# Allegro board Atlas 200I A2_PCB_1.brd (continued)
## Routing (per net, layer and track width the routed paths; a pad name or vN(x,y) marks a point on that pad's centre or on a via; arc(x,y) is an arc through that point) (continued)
VBUS_USB_TYPEC: length 2.5
  TOP w0.254: J4.21 104.6,6.16 J4.4 ; J4.16 107.1,6.16 J4.9
  vias: v1(101.04,10.62)
/CLKREQ_M2: length 2.7
  TOP w0.203: R34.1 R26.1 113.92,30.6 113.96,30.64 J1.52
/CLKREQ_WIFI: length 140.6
  TOP w0.203: v1(7.49,74.8) R70.1 7.39,75.54 6.58,76.35 R42.2 ; J16.319 98.5,59 v1(99.06,59.56)
  BOTTOM w0.203: v1(99.06,59.56) 99.63,60.13 99.63,61.21 97.82,63.02 74.23,63.02 69.38,58.17 67.12,58.17 66.59,58.71 66.59,60.24 65.93,60.89 64.38,60.89 64.11,61.16 64.11,66.76 64.6,67.95 65.95,69.29 69.15,70.62 71.41,72.88 71.41,73.26 71.14,73.53 70.58,73.53 67.79,76.32 67.79,76.36 66.38,77.77 60.38,77.77 54.47,71.87 30.07,71.87 29.85,72.09 24.27,72.09 22.48,70.29 22.48,66.92 22.21,66.65 16.41,66.65 11.91,71.15 9.45,71.15 7.49,73.1 v1(7.49,74.8)
/EMMC_RESET: length 64.2
  TOP w0.203: J16.203 v1(47,59.61) ; R79.1 22.56,93.65 22.81,93.9 22.81,95.93 v1(22.21,96.52) ; v1(43.34,82.07) 44.07,82.07 44.69,81.45 R202.2 45.13,80.92 45.34,80.72 45.34,79.15 v1(45.97,78.52)
  ART03 w0.203: v1(45.97,78.52) 46.51,77.99 46.51,73.63 47.35,72.8 47.35,63.04 47,62.7 v1(47,59.61)
  ART04 w0.203: v1(43.34,82.07) 45.04,83.77 45.04,86 35.61,95.43 29.27,95.43 27.57,97.13 22.82,97.13 v1(22.21,96.52)
/EMMC_RESET_R: length 17.4
  TOP w0.127: v1(8.06,97.03) 7.95,96.91 U27.K5
  TOP w0.203: C87.2 R77.2 v1(22.16,95.1)
  ART04 w0.203: v1(22.16,95.1) 10.79,95.1 8.87,97.03 v1(8.06,97.03)
/LED_PHY0_ACT: length 71.1
  TOP w0.203: v1(8.1,57.53) 8.35,57.28 8.35,56.01 8.56,55.79 U1.37 ; v1(35,26.67) R365.2 ; R98.2 R140.1 v1(22.05,63.7) 21.72,63.38 21.72,63.25 20.93,62.46 15.21,62.46 v1(15.04,62.28)
  BOTTOM w0.203: v1(15.04,62.28) 14.35,61.59 9.73,61.59 8.28,60.15 8.28,57.72 v1(8.1,57.53)
  BOTTOM w0.254: v1(22.05,63.7) 24,61.75 24,56.64 18.75,51.38 18.75,44.81 29.14,34.41 32.09,34.41 35.18,31.32 35.18,26.85 v1(35,26.67)
/LED_PHY0_LINK: length 103.7
  TOP w0.203: v1(8.86,57.53) 9.26,57.12 9.73,57.12 9.95,56.9 U1.35 ; R99.2 v1(24.46,71.63) R138.1 ; v1(35,22.61) R366.2
  ART03 w0.203: v1(24.46,71.63) 23.57,71.63 22.96,71.02 16.48,71.02 8.86,63.39 v1(8.86,57.53)
  BOTTOM w0.203: v1(24.46,71.63) 29.73,71.63 35.05,66.31 35.05,61.91 30.06,56.92 26.31,56.92 19.18,49.79 19.18,45.61 28.8,35.99 31.49,35.99 36.32,31.15 36.32,30.11 35.66,29.44 35.66,26.68 35.12,26.15 34.85,26.15 34.54,25.84 34.54,23.06 v1(35,22.61)
/LED_PHY1_ACT: length 31.4
  TOP w0.203: v1(35,25.65) R367.2 ; v1(47.8,37.29) 47.48,37.61 47.48,38.61 47.93,39.07 49.38,39.07 49.76,38.68 R146.1 49.99,38.71 51.94,38.71 52.17,38.94 R154.2 52.43,39.24 54.48,37.19 54.48,36.57 54.69,36.36 U2.37
  BOTTOM w0.203: v1(47.8,37.29) 46.94,37.29 46.48,36.83 44.31,36.83 42.57,35.09 42.57,33.77 39.12,30.32 38.63,30.12 37.8,29.29 37.8,27.99 35.46,25.65 v1(35,25.65)
/LED_PHY1_LINK: length 38.5
  TOP w0.203: v1(35,23.62) R368.2 ; U2.35 56.11,37.61 v1(55.88,37.85) 55.61,38.12 54.72,38.12 53.54,39.29 53.54,41.5 53.26,41.79 R155.2 53.11,42.04 R144.1
  BOTTOM w0.203: v1(55.88,37.85) 55.55,38.18 50.17,38.18 48.36,36.37 47.25,36.37 46.84,35.97 44.67,35.97 43.43,34.73 43.43,29.85 42.55,28.96 42.55,28.07 38.1,23.62 v1(35,23.62)
/OC0_USB30_REAR_1: length 141.9
  TOP w0.203: v1(90.33,101.83) 90.21,101.83 89.89,102.15 U38.25 89.89,104.07 89.69,104.27 88.74,104.27 R598.1 ; v1(87.9,69.22) R545.1
  ART03 w0.203: v1(87.9,69.22) 90.2,69.22 90.3,69.11 91.76,69.11 91.85,69.03 92.23,69.03 92.32,69.11 96.98,69.11 97.28,69.42 97.28,73.2 95.83,74.65 95.83,75.73 v1(97.07,76.96)
  ART04 w0.203: v1(97.07,76.96) 97.55,76.48 99.92,76.48 100.91,75.49 100.91,74.04 101.4,73.56 108.5,73.56 108.7,73.36 117.25,73.36 119.99,70.61 122.73,70.61 122.87,70.47 123.89,70.47 125.12,71.7 126.11,71.7 130.01,75.6 130.01,77.24 129.21,78.04 129.21,82.68 130.01,83.48 130.01,83.86 129.78,84.09 129.78,95.93 130.72,96.87 130.72,100.62 129.79,101.55 123.95,101.55 123.52,101.12 121.58,101.12 120.89,101.8 106.72,101.8 104.43,99.52 99.94,99.52 99.39,100.07 99.39,104.51 97.47,106.43 95.15,106.43 93.57,108 93.57,108.4 93.29,108.69 92.89,108.69 90.33,106.13 v1(90.33,101.83)
/OC0_USB30_REAR_2: length 54.9
  TOP w0.203: v1(72.84,70.99) 73.07,70.76 R645.1 ; R646.1 93.9,101.09 v1(93.55,101.09) 93.55,101.14 93.32,101.37 U38.18
  ART04 w0.203: v1(84.62,101.51) 85.77,100.36 92.81,100.36 v1(93.55,101.09)
  BOTTOM w0.203: v1(84.62,101.51) 83.81,100.71 83.81,99.64 79.4,95.22 79.4,83.78 78.32,82.7 77.23,82.7 74.47,79.95 74.47,77.25 73.88,76.65 73.69,76.65 72.54,75.5 72.54,72.31 72.84,72 v1(72.84,70.99)
/OC1_USB30_REAR_1: length 14.3
  TOP w0.203: R546.2 R544.1 86.45,72.91 86.2,73.16 86.12,73.16 v1(85.8,73.48) ; U36.67 91.68,80.22 91.88,80.02 91.88,79.5 v1(92.14,79.25)
  ART03 w0.203: v1(85.8,73.48) 86.12,73.81 86.12,74.21 86.94,75.03 87.81,75.03 92.02,79.25 v1(92.14,79.25)
/OC1_USB30_REAR_2: length 19.8
  TOP w0.203: U36.10 95.35,76.4 95.55,76.61 v1(95.83,76.61) ; R644.1 R643.2 82.7,70.76 v1(84.58,72.64)
  ART03 w0.203: v1(84.58,72.64) 87.2,72.64 88.14,73.58 94.77,73.58 95.38,74.2 95.38,76.15 v1(95.83,76.61)
/OC_USB30_REAR_1: length 76.6
  TOP w0.203: v1(48.26,31.5) 48.26,30.94 R647.1 47.44,30.85 U8.3 ; R544.2 R545.2 86,68.76 82.27,68.76 82.02,69.01 70.43,69.01 v1(69.98,69.47)
  ART03 w0.203: v1(53.09,40.39) 53.09,36.32 v1(48.26,31.5) ; v1(69.98,69.47) 69.56,69.89 65.96,69.89 62.17,66.1 62.17,55.42 57.45,50.7 v1(54.69,50.7)
  ART04 w0.203: v1(53.09,40.39) 53.54,40.84 53.54,41.51 52.17,42.88 52.17,44.19 53.04,45.06 55.59,45.06 57.15,46.62 57.15,47.83 54.69,50.29 v1(54.69,50.7)
/OC_USB30_REAR_2: length 105.8
  TOP w0.203: v1(59.44,16.76) 59.44,16.13 59.23,15.93 R648.1 58.56,16.29 U9.3 ; R644.2 R645.2 71.35,69.95 v1(70.87,69.47)
  ART03 w0.203: v1(57.02,41.27) 58.04,42.29 58.04,45.55 57.81,45.77 57.81,46.17 58.32,46.68 58.32,47.6 62.58,51.86 62.58,65.93 66.13,69.48 69.32,69.48 69.79,69.01 70.41,69.01 v1(70.87,69.47) ; v1(59.44,16.76) 54.51,16.76 50.27,21 47.88,21 44.33,24.56 40.57,24.56 39.99,25.14 39.99,27.67 39.75,27.91 38.36,27.91 37.84,28.42 37.84,29.33 38.2,29.69 38.85,29.69 44,34.84 44,37.9 v1(45.09,38.99)
  BOTTOM w0.203: v1(57.02,41.27) 57.02,41.73 56.16,42.6 53.29,42.6 52.32,41.63 49.63,41.63 49.58,41.68 49.18,41.68 46.69,39.19 45.29,39.19 v1(45.09,38.99)
/PERST_M2: length 39.4
  TOP w0.203: J16.296 103.75,50.47 v1(103.58,50.65) ; R12.2 R678.1 v1(119.25,68.23)
  ART03 w0.203: v1(103.58,50.65) 104.36,51.44 104.36,55.42 108.46,59.52 108.46,71.41 109.12,72.06 v1(109.12,72.39)
  ART04 w0.203: v1(119.25,68.23) 115.86,71.63 109.88,71.63 v1(109.12,72.39)
/PERST_M2_R: length 65.4
  TOP w0.203: U21.13 118.75,76.51 v1(119.08,76.18) ; R32.1 R27.1 C34.1 111.71,31.59 v1(111.83,31.46)
  TOP w0.254: R23.2 v1(111.83,31.46)
  ART03 w0.203: v1(108.25,76.94) 109.33,76.94 109.73,76.54 109.73,72.02 109.27,71.57 109.27,62.56 v1(111.43,60.4)
  ART04 w0.203: v1(108.25,76.94) 109.6,76.94 110.9,75.64 118.53,75.64 v1(119.08,76.18)
  BOTTOM w0.203: v1(111.83,31.46) 111.83,33.1 111.05,33.88 111.05,44.5 110.52,45.03 110.52,59.49 v1(111.43,60.4)
/PERST_WIFI: length 35.3
  TOP w0.203: R626.1 110.52,76.47 R566.2 ; v1(106.6,54.2) 106.6,54.1 104.25,51.75 J16.294
  TOP w0.254: R566.2 v1(111.45,76.32)
  ART03 w0.203: v1(111.45,76.32) 111.45,69.01 111.02,68.58 111.02,66.69 112.94,64.78 112.94,58.94 111.37,57.37 111.24,57.37 109.95,56.08 108.02,56.08 106.6,54.66 v1(106.6,54.2)
/PERST_WIFI_R: length 93.1
  TOP w0.203: v1(7.11,80.9) 7.11,82.25 8.26,83.39 9.14,83.39 9.42,83.67 J2.52 9.42,85.67 9.22,85.88 8.53,85.88 7.86,86.55 R39.1 ; R618.2 73.8,79.49 v1(73.79,79.5)
  ART03 w0.203: v1(52.45,79.63) 52.45,72.75 v1(52.04,72.35)
  ART04 w0.203: v1(7.11,80.9) 7.16,80.85 7.16,77.45 7.01,77.3 7.01,74.6 7.93,73.69 9.47,73.69 12.01,71.15 24.66,71.15 24.96,71.44 51.14,71.44 v1(52.04,72.35)
  BOTTOM w0.203: v1(52.45,79.63) 54.38,81.55 71.73,81.55 v1(73.79,79.5)
/PEWAKE_M2: length 3.7
  TOP w0.203: J1.54 114.24,30.14 114.05,29.95 114.05,29.1 113.84,28.89 R33.1 R28.1
/PEWAKE_WIFI: length 7
  TOP w0.203: v1(99.06,58.29) 99,58.23 J16.317 ; R625.1 R571.2 v1(98.6,61.5)
  ART03 w0.203: v1(99.06,58.29) 98.6,58.75 v1(98.6,61.5)
/PEWAKE_WIFI_R: length 86.1
  TOP w0.203: R41.2 5.41,76.35 4.6,75.54 R43.1 v1(4.45,74.8) ; R617.2 v1(73.88,83.12)
  ART03 w0.203: v1(51.18,79.63) 51.66,79.15 51.66,78.23 51.56,78.13 51.56,71.56 v1(52.04,71.08)
  ART04 w0.203: v1(4.45,74.8) 7.87,71.37 9.93,71.37 11.43,69.88 24.71,69.88 25.82,70.99 51.33,70.99 51.34,71 51.96,71 v1(52.04,71.08)
  BOTTOM w0.203: v1(51.18,79.63) 54.05,82.5 73.25,82.5 v1(73.88,83.12)
/RST_USB_HUB_R: length 5.5
  TOP w0.203: U38.24 90.29,104.81 R633.2 C367.1 ; C367.1 R639.2 ; C367.1 90.53,106.25 R632.2
/SDIO_RESET_R: length 19.3
  TOP w0.203: v1(15.95,79.86) 16.68,79.13 J2.23 ; v1(20.95,92.08) 21.4,92.08 R79.2
  ART03 w0.203: v1(15.95,79.86) 15.34,80.47 15.34,81.38 15.44,81.48 15.44,82.22 15.44,82.22 15.44,82.39 16.55,83.5 16.55,84.09 18.39,85.92 18.39,86.38 19.38,87.38 20.57,87.38 21.44,88.24 21.44,91.59 v1(20.95,92.08)
/SDIO_WAKE_R: length 79.8
  TOP w0.203: J2.21 17.17,79.19 16.54,79.83 16.54,80.54 v1(15.95,81.13) ; J16.121 67.5,54.46 v1(67.5,54.46) ; R80.2 v1(22.23,86.36)
  ART03 w0.203: v1(15.95,81.13) 16.05,81.23 16.05,82.14 17.16,83.25 17.16,83.83 17.8,84.47 18.2,84.47 19.44,85.71 19.44,86.37 19.72,86.65 21.93,86.65 v1(22.23,86.36) ; v1(38.95,70.09) 38.95,70.7 33.94,75.71 33.94,81.75 v1(30.1,85.6)
  ART04 w0.203: v1(67.5,54.46) 67.5,54.82 65.15,57.16 65.15,59.22 54.27,70.09 v1(38.95,70.09)
  BOTTOM w0.203: v1(30.1,85.6) 22.99,85.6 v1(22.23,86.36)
/WAKE_PHY0: length 21.2
  TOP w0.203: R624.1 R569.2 R217.2 68.75,72.44 63.58,67.26 63.58,59.7 62.5,58.62 J16.141
/WAKE_PHY0_R: length 74.3
  TOP w0.203: R616.2 74.13,83.98 v1(73.88,84.23) ; v1(19.02,60.73) 19.74,60.02 20.83,60.02 R125.1 21.08,60.27 R101.1 R124.2
  ART03 w0.203: v1(19.02,60.73) 19.02,63.8 22.02,66.8 v1(22.02,67.11)
  BOTTOM w0.203: v1(22.02,67.11) 22.02,70.73 23.83,72.53 23.83,72.84 24.36,73.38 24.54,73.38 27.85,76.69 46.84,76.69 55.25,85.1 73.01,85.1 v1(73.88,84.23)
/WAKE_PHY1: length 54.4
  TOP w0.203: R621.1 v1(87.63,85.81) ; v1(99.06,60.83) 98.67,60.44 R565.2 R235.2 98,59.58 J16.321
  ART03 w0.203: v1(99.06,60.83) 99.87,61.65 99.87,66.48 102.64,69.25 102.64,74.83 102.67,74.85 102.67,80.19 101.94,80.91 101.94,83.53 v1(103.89,85.47)
  ART04 w0.203: v1(87.63,85.81) 87.17,85.81 85.99,84.63 85.99,84.23 86.29,83.93 90.47,83.93 90.73,84.2 92.31,84.2 92.79,84.68 101.69,84.68 102.48,85.47 v1(103.89,85.47)
/WAKE_PHY1_R: length 78
  TOP w0.203: R168.1 54.08,41.25 v1(54.23,41.4) 54.12,41.51 R192.2 54.35,42.04 54.68,42.37 R193.1 ; v1(73.88,85.34) 74.38,84.83 R613.2
  ART03 w0.203: v1(50.14,65.57) 50.04,65.67 v1(50.04,78.61)
  ART04 w0.203: v1(54.23,41.4) 52.58,43.05 52.58,43.5 52.85,43.76 53.59,43.76 53.85,43.51 55.37,43.51 56.67,44.81 56.67,45.06 57.1,45.49 57.48,45.49 57.76,45.77 57.76,46.28 58.27,46.79 58.27,48.98 54.55,52.7 53.36,52.7 50.87,55.19 50.87,59.79 50.14,60.53 v1(50.14,65.57)
  BOTTOM w0.203: v1(50.04,78.61) 50.04,79.22 54.41,83.59 73.88,83.59 74.33,84.04 74.33,84.88 v1(73.88,85.34)
/WAKE_UART3: length 2.9
  TOP w0.203: R44.2 17.02,88.62 17.53,89.13 R48.1
AC_IN_L: length 42.3
  TOP w0.254: v1(131.85,40.84) 132.54,40.84 132.79,40.59 132.79,40.31 132.97,40.13 C149.1 LB12.2 ; J16.306 101.25,47.15 v1(100.97,46.86)
  ART03 w0.254: v1(131.85,40.84) 131.27,40.27 130.73,40.27 130.19,40.81 130.19,44.23 127.83,46.58 112.99,46.58 112.4,46 105.95,46 104.98,45.03 102.34,45.03 100.97,46.41 v1(100.97,46.86)
AC_IN_R: length 38.9
  TOP w0.254: v1(131.09,40.84) 131.09,41.51 C148.1 130.49,41.51 130.37,41.39 LB11.2 ; J16.304 101.75,46.97 v1(101.85,46.86)
  ART03 w0.254: v1(131.09,40.84) 130.89,41.05 130.89,44.47 128.11,47.24 112.71,47.24 112.13,46.66 105.68,46.66 104.71,45.69 102.98,45.69 101.85,46.82 v1(101.85,46.86)
AC_MICBIAS0: length 43.3
  TOP w0.203: J16.300 102.75,47.62 v1(103.5,46.86) ; R314.2 v1(134.24,36.12)
  ART03 w0.203: v1(103.5,46.86) 103.63,46.99 104.17,46.99 105.13,47.96 111.59,47.96 112.17,48.54 128.64,48.54 132.18,45 132.18,42.42 133.15,41.46 133.15,37.21 v1(134.24,36.12)
BOARD_ID0: length 5.2
  TOP w0.203: U19.4 120.49,94.04 121.34,93.19 R523.2 121.54,92.89 121.74,92.68 123.37,92.68 123.62,92.94 R507.1
BOARD_ID1: length 5
  TOP w0.203: U19.5 120.6,94.69 121.08,94.21 R522.2 121.54,93.9 121.74,93.7 123.37,93.7 123.62,93.95 R506.1
BOARD_ID2: length 4.9
  TOP w0.203: R505.1 123.62,94.97 123.37,94.72 121.74,94.72 121.54,94.92 R521.2 120.81,95.22 120.7,95.34 U19.6
BOARD_ID3: length 4.9
  TOP w0.203: U19.7 120.78,95.99 121.03,96.24 R520.2 121.54,95.94 121.74,95.73 123.37,95.73 123.62,95.99 R504.1
BOARD_ID4: length 5.1
  TOP w0.203: R503.1 123.62,97 123.37,96.75 121.74,96.75 121.54,96.95 R519.2 120.92,96.64 U19.8
BOARD_ID5: length 5.2
  TOP w0.203: 121.54,98.22 R518.2 ; 121.54,98.22 121.54,97.97 121.74,97.76 123.37,97.76 123.62,98.02 R502.1 ; 121.54,98.22 120.6,97.29 U19.9
BOARD_ID6: length 5.5
  TOP w0.203: U19.10 120.39,97.94 120.88,98.42 120.88,98.63 R517.2 121.54,98.98 121.74,98.78 123.37,98.78 123.62,99.03 R501.1
BOARD_ID7: length 10
  TOP w0.203: R500.1 123.62,100.05 123.37,99.8 121.74,99.8 121.54,100 R516.2 120.73,100.3 120.17,99.75 118.08,99.75 117.55,99.21 117.55,98.65 117.75,98.45 118.28,98.45 118.41,98.59 U19.11
BOM_ID0: length 6.1
  TOP w0.203: R508.1 109.27,100.99 109.55,100.71 111.12,100.71 111.35,100.94 R524.2 112.32,100.25 112.32,99.84 112.92,99.24 U19.13
BOM_ID1: length 5.9
  TOP w0.203: R509.1 109.27,99.97 109.55,99.69 111.12,99.69 111.35,99.92 R525.2 111.91,99.64 111.91,99.36 112.69,98.59 U19.14
BOM_ID2: length 5.5
  TOP w0.203: U19.15 112.6,97.94 R526.2 111.35,98.91 111.12,98.68 109.55,98.68 109.27,98.96 R510.1
BOOT_SEL0: length 85.3
  TOP w0.203: v1(119.38,51.18) 119.41,51.16 129.01,51.16 130.31,52.46 SW1.2 ; J16.137 63.5,58.37 67.46,62.33 80.87,62.33 85.69,67.16 94.77,67.16 v1(95.63,66.29)
  ART04 w0.203: v1(95.63,66.29) 99.64,66.29 100.97,67.61 101.12,67.61 101.46,67.96 106.81,67.96 110.13,64.63 110.13,63.11 116.1,57.14 116.1,53.82 117.86,52.07 118.49,52.07 v1(119.38,51.18)
BOOT_SEL1: length 83
  TOP w0.203: v1(118.11,51.18) 118.62,51.69 126.85,51.69 127.77,52.61 SW1.3 ; v1(94.74,66.29) 94.28,66.75 85.86,66.75 81.04,61.93 67.63,61.93 64,58.3 J16.135
  ART04 w0.203: v1(94.74,66.29) 95.35,65.68 99.77,65.68 101.61,67.52 106.67,67.52 109.09,65.1 109.09,61.06 111.24,58.9 112.71,58.9 114.79,56.83 114.79,56.04 115.7,55.13 115.7,53.34 117.86,51.18 v1(118.11,51.18)
BOOT_SEL2: length 75.4
  TOP w0.203: v1(93.73,66.29) 85.98,66.29 81.2,61.52 67.8,61.52 64.5,58.22 J16.133 ; v1(116.84,51.18) 117.78,52.12 125.02,52.12 125.23,52.33 SW1.4
  ART04 w0.203: v1(93.73,66.29) 95.81,64.21 100.09,64.21 103.55,60.75 108.4,60.75 113.19,55.96 114.01,55.96 115.29,54.67 115.29,52.73 v1(116.84,51.18)
BPWR_DET_USB2: length 62.5
  TOP w0.203: v1(93.59,76.99) 92.82,76.99 92.15,76.31 U36.2 ; v1(87.33,73.48) 87.33,73.03 88.16,72.19 R460.2 ; R632.1 v1(91.14,107.72)
  ART03 w0.203: v1(87.33,73.48) 87.83,73.99 94.16,73.99 94.82,74.65 94.82,75.76 v1(93.59,76.99) 93.59,79.1 94.25,79.76 94.27,79.76 94.54,80.03 94.54,80.05 95.52,81.03 95.54,81.03 95.81,81.3 95.81,81.32 97.47,82.98 98.35,82.98 101.67,86.3 101.67,86.76 102.34,87.43 102.34,88.35 103.12,89.13 103.12,90.41 104.95,92.23 104.95,96.48 100.52,100.91 99.3,100.91 97.95,102.26 95.46,102.26 94.82,101.62 93.19,101.62 91.14,103.67 v1(91.14,107.72)
BPWR_VL817_HUB1: length 8.5
  TOP w0.203: U38.45 84.45,99.37 v1(84.67,99.15) ; R577.1 v1(81.66,104.78)
  ART04 w0.203: v1(81.66,104.78) 81.66,102.75 84,100.41 84,99.82 v1(84.67,99.15)
CARD_DETECT: length 15.3
  TOP w0.203: R234.2 22.99,105.69 22.99,105.03 22.79,104.84 U4.6
  TOP w0.381: J3.9 16.05,101.77 v1(15.24,100.97) ; v1(21,105.53) 21.69,104.84 U4.6
  ART04 w0.203: v1(21,105.53) 20.33,105.53 20.07,105.79 16.97,105.79 15.24,104.06 v1(15.24,100.97)
CFG_PHY0_LDO0: length 24.2
  TOP w0.203: v1(19.71,51.66) 19.71,52.28 24.1,56.67 24.1,58.62 23.67,59.05 R139.1 23.55,59.48 23.55,60.25 R97.2 ; v1(8.86,56.52) 9.51,56.52 U1.36
  ART04 w0.203: v1(8.86,56.52) 12.52,56.52 14.33,54.71 16.66,54.71 v1(19.71,51.66)
CFG_PHY1_LDO0: length 6
  TOP w0.203: R145.1 R153.2 52.58,40.13 53.14,39.57 53.14,39.11 55.2,37.04 U2.36
CLK_100M_BUF_M2_L1_N: length 15.7
  TOP w0.155: R327.1 72.26,113.06 72.01,113.06 71.65,112.7 71.65,111.53 69.67,109.55 61.87,109.55 61.4,110.02 61.4,110.87 61.46,110.93 U10.7
CLK_100M_BUF_M2_L1_P: length 16.2
  TOP w0.155: U10.6 60.96,110.93 61.02,110.87 61.02,109.86 61.72,109.17 69.83,109.17 72.03,111.37 72.03,112.54 72.16,112.67 72.44,112.67 R328.1
CLK_100M_BUF_M2_N: length 152.9
  TOP w0.155: v1(76.27,113.39) 76.04,113.16 75.46,113.16 C173.2 ; J1.53 122.4,30.39 122.46,30.34 122.95,30.34 R13.1 123.36,30.31 124.12,30.31 v1(124.39,30.59)
  ART04 w0.14: v1(76.27,113.39) 76.5,113.16 77.22,113.16 77.88,112.5 77.88,110.87 76.76,109.75 76.05,109.75 75.85,109.55 75.85,109.25 75.6,109 75.3,109 75.05,108.75 75.05,108.46 74.81,108.21 74.51,108.21 74.26,107.96 74.26,107.67 74.02,107.42 73.72,107.42 73.34,107.04 73.34,106.87 72.97,106.49 72.79,106.49 62.23,95.93 62.23,91.62 60.35,89.74 60.35,76.46 63,73.81 67.23,73.81 68.2,74.78 77.52,74.78 82.28,70.03 84.49,70.03 87.33,67.18 97.64,67.18 99.22,68.77 107.65,68.77 114.13,62.28 114.13,61.49 117.12,58.5 117.12,54.69 118.69,53.11 120.14,53.11 122.5,50.75 122.5,49.48 127.03,44.96 127.03,35.71 126.46,35.15 126.46,34.35 123.7,31.59 123.7,30.54 123.92,30.31 124.12,30.31 v1(124.39,30.59)
CLK_100M_BUF_M2_P: length 152.3
  TOP w0.155: C172.2 75.49,112.78 75.97,112.78 v1(76.24,112.5) ; v1(124.39,29.66) 124.12,29.93 123.36,29.93 R13.2 122.9,29.95 122.46,29.95 122.4,29.9 J1.55
  ART04 w0.14: v1(124.39,29.66) 124.12,29.93 123.76,29.93 123.32,30.38 123.32,31.75 126.08,34.51 126.08,35.3 126.64,35.87 126.64,44.8 122.12,49.32 122.12,50.59 119.98,52.73 118.54,52.73 116.74,54.53 116.74,58.34 113.75,61.33 113.75,62.12 107.49,68.39 99.38,68.39 97.8,66.8 87.17,66.8 84.33,69.65 82.12,69.65 77.37,74.4 68.35,74.4 67.39,73.43 62.84,73.43 59.97,76.3 59.97,89.9 61.85,91.78 61.85,96.09 75.9,110.13 76.61,110.13 77.5,111.02 77.5,112.34 77.06,112.78 76.52,112.78 v1(76.24,112.5)
CLK_100M_BUF_SLOT_L1_N: length 7.9
  TOP w0.155: R325.1 53.51,112.64 54.09,112.64 56.2,110.54 58.53,110.54 58.9,110.91 58.9,111.35 58.96,111.41 U10.2
CLK_100M_BUF_SLOT_L1_P: length 7.3
  TOP w0.155: U10.1 58.46,111.41 58.52,111.35 58.52,111.07 58.37,110.92 56.36,110.92 54.25,113.02 53.5,113.02 R326.1
CLK_100M_BUF_WIFI_L1_N: length 7.5
  TOP w0.155: U10.12 63.96,110.93 63.9,110.87 63.9,110.65 64.06,110.49 66.06,110.49 66.55,110.98 66.55,112.91 66.93,113.28 67.38,113.28 67.54,113.44 R324.1
CLK_100M_BUF_WIFI_L1_P: length 8.3
  TOP w0.155: U10.11 63.46,110.93 63.52,110.87 63.52,110.49 63.9,110.11 66.22,110.11 66.93,110.82 66.93,112.75 67.08,112.9 67.38,112.9 67.54,112.75 R323.1
CLK_100M_BUF_WIFI_N: length 114.6
  TOP w0.155: v1(8.68,74.82) 8.95,75.1 8.95,75.86 R40.2 9.07,76.4 9.07,76.5 9.17,76.61 9.17,76.61 9.57,77.01 10.08,77.01 10.23,77.17 10.23,77.27 10.17,77.33 J2.49 ; v1(71.12,113.48) 70.84,113.21 70.38,113.21 C168.2
  ART04 w0.14: v1(8.68,74.82) 8.94,75.08 8.94,76.34 11.82,79.22 34.67,79.22 36.63,77.27 47.42,77.27 51.66,81.51 51.66,105.84 48.72,108.79 48.72,115.98 49.83,117.09 56.85,117.09 58.52,115.42 58.52,114.71 60.02,113.22 70.85,113.22 v1(71.12,113.48)
CLK_100M_BUF_WIFI_P: length 113.8
  TOP w0.155: J2.47 10.68,77.3 10.62,77.24 10.62,77.01 10.24,76.63 9.73,76.63 9.55,76.45 R40.1 9.33,75.86 9.33,75.1 v1(9.61,74.82) ; v1(71.12,112.55) 70.84,112.83 70.36,112.83 C169.2
  ART04 w0.14: v1(9.61,74.82) 9.32,75.11 9.32,76.18 11.98,78.84 34.51,78.84 36.47,76.89 47.57,76.89 52.04,81.36 52.04,106 49.1,108.95 49.1,115.82 49.99,116.71 56.69,116.71 58.14,115.27 58.14,114.55 59.86,112.84 70.83,112.84 v1(71.12,112.55)
CLK_100M_M2_L2_N: length 1.9
  TOP w0.155: R327.2 C173.1 R335.1
CLK_100M_M2_L2_P: length 1.8
  TOP w0.155: C172.1 R328.2 R336.1
CLK_100M_OSC: length 11
  TOP w0.203: R3.2 C95.1 70.68,117.47 69.67,116.46 R345.2 68.58,116.46 R344.2 67.59,116.56 R340.1 66.24,116.56 65.24,116.15 U10.20
CLK_100M_SLOT1_L2_N: length 1.7
  TOP w0.155: R337.1 C171.1 R325.2
CLK_100M_SLOT1_L2_P: length 1.7
  TOP w0.155: R338.1 C170.1 R326.2
CLK_100M_WIFI_L2_N: length 1.9
  TOP w0.155: R324.2 68.35,113.54 C168.1 69.24,114.55 R333.1
CLK_100M_WIFI_L2_P: length 1.9
  TOP w0.155: R334.1 C169.1 R323.2
CLKIN_SEL0: length 8.3
  TOP w0.203: R330.1 71.91,116.2 v1(71.63,115.93) ; U10.19 65.51,115.65 v1(65.56,115.69)
  ART03 w0.203: v1(65.56,115.69) 65.99,116.13 71.42,116.13 v1(71.63,115.93)
CLKIN_SEL1: length 12.9
  TOP w0.203: U10.22 65.08,117.15 65.66,117.73 v1(65.66,117.86) ; R329.1 v1(75.21,114.94)
  ART03 w0.203: v1(75.21,114.94) 74.73,115.42 72.85,115.42 71.43,116.84 66.67,116.84 v1(65.66,117.86)
CLKOUTA_TYPE0: length 13.6
  TOP w0.203: U10.14 64.96,113.15 65.41,112.7 65.41,111.51 v1(65.02,111.12) ; R317.1 R316.2 71.86,114.4 v1(71.63,114.17)
  ART03 w0.203: v1(71.63,114.17) 71.63,112.17 70.58,111.12 v1(65.02,111.12)
CLKOUTA_TYPE1: length 5.3
  TOP w0.203: R318.1 R322.2 54.82,113.15 U10.47
DEVSLP_M2: length 4
  TOP w0.203: R25.1 R24.1 112.24,37.44 112.39,37.59 113.16,37.59 113.54,37.21 R22.2
DSI_I2C_INT: length 41.1
  TOP w0.203: J16.227 41.05,56.37 41.05,56.73 41,56.78 41,57.94 40.74,58.2 40.74,59.94 41.28,60.48 41.58,60.48 51.41,70.31 52.07,70.31 60.86,79.1 67.63,79.1 68.99,80.45 R627.1
DSI_I2C_INT_R: length 96.9
  TOP w0.203: R425.1 v1(9.27,73.03) ; v1(78.34,83.4) 78.01,83.08 U25.13
  ART04 w0.203: v1(9.27,73.03) 7.57,73.03 4.77,75.83 1.45,75.83 1.17,76.11 1.17,77.03 2.24,78.11 2.24,79 5.27,82.02 5.95,82.02 6.27,82.35 7.64,82.35 7.95,82.04 11.3,82.04 11.6,81.74 14.99,81.74 15.32,82.07 21.25,82.07 22.47,80.85 36.96,80.85 37.19,81.08 43.91,81.08 v1(46.69,83.85)
  BOTTOM w0.203: v1(78.34,83.4) 75.92,85.82 73.68,85.82 73.45,85.6 51.69,85.6 49.47,83.37 47.17,83.37 v1(46.69,83.85)
EMMC_CLK: length 53.8
  TOP w0.203: v1(26.67,90.81) 26.67,88.27 26.34,87.93 R86.1 ; J16.199 v1(48,59.58) ; v1(40.55,84.86) 40.8,85.12 R216.1 42.22,85.12 42.74,84.6 v1(42.74,84.35)
  ART03 w0.203: v1(42.74,84.35) 42.97,84.12 43.69,84.12 48.56,79.25 48.56,60.76 48,60.2 v1(48,59.58)
  ART04 w0.203: v1(26.67,90.81) 35.06,90.81 40.55,85.32 v1(40.55,84.86)
EMMC_CLK_R: length 32.1
  TOP w0.127: v1(6.65,97.41) 7.06,97.82 U27.M6
  TOP w0.203: R71.2 v1(26.04,89.53) 26.04,90.14 25.37,90.8 25.37,91.19 C86.2
  ART04 w0.203: v1(26.04,89.53) 25.96,89.53 25.35,90.14 23.42,90.14 22.83,89.56 22.83,89.46 22.43,89.05 17.78,89.05 16.79,90.04 10.11,90.04 9.81,90.35 7.93,90.35 7.32,90.95 6.79,90.95 6.5,91.24 6.5,91.97 7.81,93.28 7.81,94.12 7.42,94.51 7.42,96.65 v1(6.65,97.41)
EMMC_CMD: length 57.5
  TOP w0.203: R72.1 26.19,93.65 27.36,94.82 v1(27.36,96.48) ; v1(43.34,83.46) 43.53,83.46 45.95,81.05 45.95,80.95 R203.2 46.42,80.92 46.62,80.72 46.62,79.15 v1(47.26,78.52) ; J16.201 v1(47.5,58.84)
  ART03 w0.203: v1(47.26,78.52) 47.96,77.82 47.96,61.56 47.5,61.1 v1(47.5,58.84)
  ART04 w0.203: v1(43.34,83.46) 43.49,83.46 44.43,84.41 44.43,85.74 35.36,94.82 29.02,94.82 v1(27.36,96.48)
EMMC_CMD_R: length 23.7
  TOP w0.127: v1(7.41,97.42) 7.41,97.42 7.41,97.42 7.56,97.57 U27.M5
  TOP w0.203: R72.2 v1(25.97,95.1)
  ART04 w0.203: v1(25.97,95.1) 25.58,95.1 24.95,95.73 22.15,95.73 20.76,97.11 17.17,97.11 16.96,96.91 16.96,96.6 16.76,96.39 16.35,96.39 16.15,96.6 16.15,96.91 15.95,97.11 15.43,97.11 15.23,96.91 15.23,96.77 15.03,96.57 14.62,96.57 14.42,96.77 14.42,96.91 14.22,97.11 13.81,97.11 13.61,96.91 13.61,96.77 13.4,96.57 13,96.57 12.79,96.77 12.79,96.91 12.59,97.11 12.18,97.11 11.98,96.91 11.98,96.77 11.78,96.57 11.37,96.57 10.2,97.74 7.73,97.74 v1(7.41,97.42)
EMMC_DATA0: length 59.8
  TOP w0.203: v1(39.15,84.86) 39.81,84.2 40.59,84.2 41.18,83.61 41.18,81.98 42.11,81.05 R208.2 42.54,80.92 42.75,80.72 42.75,79.17 v1(43.4,78.52) ; v1(46,59.58) J16.207 ; v1(24.77,90.81) 24.77,90.55 25.37,89.94 25.37,88.24 25.07,87.93 R84.1
  ART03 w0.203: v1(43.4,78.52) 44.04,77.87 44.04,74.34 46.13,72.26 46.13,63.04 46,62.92 v1(46,59.58)
  ART04 w0.203: v1(24.77,90.81) 25.55,90.81 26.24,90.12 27.49,90.12 27.7,89.92 27.7,89.41 27.9,89.2 28.31,89.2 28.51,89.41 28.51,89.92 28.71,90.12 29.12,90.12 29.32,89.92 29.32,89.41 29.53,89.2 29.93,89.2 30.14,89.41 30.14,89.92 30.34,90.12 30.75,90.12 30.95,89.92 30.95,89.41 31.15,89.2 31.56,89.2 31.76,89.41 31.76,89.92 31.96,90.12 32.37,90.12 32.57,89.92 32.57,89.41 32.78,89.2 33.18,89.2 33.39,89.41 33.39,89.92 33.59,90.12 34.88,90.12 35.79,89.21 35.79,88.92 35.77,88.9 35.77,88.61 36.06,88.32 36.35,88.32 36.37,88.35 36.66,88.35 36.94,88.06 36.94,87.77 36.92,87.75 36.92,87.46 37.21,87.17 37.5,87.17 37.52,87.2 37.81,87.2 38.09,86.91 38.09,86.62 38.07,86.6 38.07,86.31 38.36,86.02 38.65,86.02 38.67,86.05 38.96,86.05 39.15,85.85 v1(39.15,84.86)
EMMC_DATA0_R: length 21.8
  TOP w0.203: v1(9.27,89.1) 9.27,89.36 8.84,89.79 8.84,91.92 8.56,92.2 U27.A3 ; R73.2 v1(24.77,89.53)
  ART04 w0.203: v1(24.77,89.53) 24.77,89.08 23.19,87.5 21.73,87.5 21.57,87.35 17.43,87.35 17.02,87.76 13.08,87.76 12.06,88.77 9.65,88.77 9.65,88.78 9.59,88.78 v1(9.27,89.1)
EMMC_DATA1: length 60.7
  TOP w0.203: v1(25.78,96.52) 25.36,96.1 25.36,93.88 25.14,93.65 R83.1 ; v1(40.55,83.46) 40.55,81.63 40.83,81.35 R209.2 41.32,80.92 41.46,80.78 41.46,79.17 v1(42.11,78.52) ; v1(45.5,58.8) J16.209
  ART03 w0.203: v1(45.5,58.8) 45.5,63.03 45.52,63.04 45.52,72.01 42.77,74.75 42.77,77.86 v1(42.11,78.52)
  ART04 w0.203: v1(25.78,96.52) 26.45,96.52 28.76,94.21 35.11,94.21 43.82,85.49 43.82,84.66 42.14,82.98 41.03,82.98 v1(40.55,83.46)
EMMC_DATA1_R: length 25.2
  TOP w0.203: R74.2 v1(24.7,95.1) ; v1(8.26,91.57) 8.06,91.76 U27.A4
  ART04 w0.203: v1(24.7,95.1) 20.94,91.34 18.89,91.34 18.69,91.54 18.69,92.3 18.48,92.51 18.08,92.51 17.87,92.3 17.87,91.54 17.67,91.34 17.26,91.34 17.06,91.54 17.06,92.3 16.86,92.51 16.45,92.51 16.25,92.3 16.25,91.54 16.05,91.34 15.64,91.34 15.44,91.54 15.44,92.3 15.23,92.51 14.83,92.51 14.62,92.3 14.62,91.54 14.42,91.34 10.54,91.34 10.31,91.57 v1(8.26,91.57)
EMMC_DATA2: length 59.4
  TOP w0.203: R82.1 23.8,87.93 24.1,88.24 24.1,90.2 v1(23.5,90.81) ; v1(40.83,78.52) 40.18,79.16 40.18,80.7 39.95,80.92 R210.2 39.54,81.77 39.63,81.87 39.63,82.98 v1(39.15,83.46) ; v1(45,59.55) J16.211
  ART03 w0.203: v1(45,59.55) 45,61.96 44.91,62.05 44.91,71.76 41.43,75.24 41.43,77.92 v1(40.83,78.52)
  ART04 w0.203: v1(39.15,83.46) 39.83,83.46 41.16,84.79 41.16,85.57 35.31,91.41 33.27,91.41 33.07,91.62 33.07,91.83 32.86,92.03 32.46,92.03 32.25,91.83 32.25,91.62 32.05,91.41 31.64,91.41 31.44,91.62 31.44,91.83 31.24,92.03 30.83,92.03 30.63,91.83 30.63,91.62 30.42,91.41 30.02,91.41 29.81,91.62 29.81,91.83 29.61,92.03 29.21,92.03 29,91.83 29,91.62 28.8,91.41 24.1,91.41 v1(23.5,90.81)
EMMC_DATA2_R: length 22.4
  TOP w0.203: U27.A5 7.56,90.64 7.5,90.58 7.5,90.55 v1(7.18,90.23) ; R75.2 v1(23.5,89.53)
  ART04 w0.203: v1(7.18,90.23) 7.67,89.74 9.55,89.74 9.86,89.43 13.73,89.43 13.93,89.23 13.93,88.85 14.14,88.65 14.54,88.65 14.74,88.85 14.74,89.23 14.95,89.43 16.21,89.43 17.68,87.96 21.32,87.96 21.47,88.11 22.53,88.11 23.5,89.08 v1(23.5,89.53)
EMMC_DATA3: length 65.5
  TOP w0.203: v1(23.48,96.52) 24.08,95.93 24.08,93.93 23.8,93.65 R81.1 ; J16.213 v1(44.5,58.78) ; v1(43.34,84.86) 42.43,85.78 39.38,85.78 38.46,84.85 38.46,81.69 38.25,81.48 R211.2 38.58,80.92 38.9,80.6 38.9,79.15 v1(39.54,78.52)
  ART03 w0.203: v1(44.5,58.78) 44.5,61.11 44.3,61.32 44.3,71.5 40.11,75.69 40.11,77.95 v1(39.54,78.52)
  ART04 w0.203: v1(43.34,84.86) 43,85.2 43,85.45 34.85,93.6 28.51,93.6 26.2,95.91 25.68,95.91 25.07,96.52 v1(23.48,96.52)
EMMC_DATA3_R: length 17.4
  TOP w0.127: U27.B2 U27.A1
  TOP w0.203: v1(11.56,91.95) 11.33,91.72 10.25,91.72 U27.A1 ; R76.2 v1(23.43,95.1)
  ART04 w0.203: v1(23.43,95.1) 23.14,95.1 22.45,94.41 13.23,94.41 11.56,92.74 v1(11.56,91.95)
EMMC_DATA4: length 78.2
  TOP w0.203: J16.215 v1(44,59.6) ; v1(13.64,86.36) R207.2 R218.1 14.37,87.88 R37.1 ; v1(37.75,83.46) 37.21,82.92 37.21,79.56 v1(38.25,78.52)
  ART03 w0.203: v1(44,59.6) 44,60.42 43.69,60.73 43.69,71.25 38.84,76.1 38.84,77.94 v1(38.25,78.52)
  ART04 w0.203: v1(13.64,86.36) 14.8,86.84 17.07,86.84 17.17,86.74 21.83,86.74 21.98,86.89 23.44,86.89 24.94,88.39 26.07,88.39 26.27,88.6 26.27,88.82 26.47,89.03 26.88,89.03 27.08,88.82 27.08,88.6 27.28,88.39 31.47,88.39 31.67,88.19 31.67,87.78 31.47,87.58 25.02,87.58 24.8,87.36 24.8,87.07 25,86.87 32.28,86.87 32.49,87.07 32.49,88.19 32.87,88.57 34.91,88.57 38.24,85.24 38.24,84.63 v1(37.75,83.46)
EMMC_DATA4_R: length 9.8
  TOP w0.127: U27.B3 U27.A2
  TOP w0.203: R218.2 12.82,90.28 12.4,90.7 11.79,90.7 10.81,89.72 10.81,89.72 10.75,89.66 9.87,89.66 9.54,89.98 9.54,91.73 9.06,92.21 U27.A2
EMMC_DATA5: length 61.6
  TOP w0.203: R37.2 14.49,87 R206.2 ; J16.217 v1(43.5,58.79) ; R206.2 R219.1 ; R206.2 v1(15.3,86.36)
  ART03 w0.203: v1(43.5,58.79) 43.5,59.98 43.08,60.4 43.08,71 36.97,77.11 36.97,84.07 v1(37.75,84.86)
  ART04 w0.203: v1(37.75,84.86) 36.36,86.26 35.87,86.26 35.66,86.46 35.66,86.89 35.46,87.1 35.05,87.1 34.85,86.89 34.85,86.46 34.65,86.26 34.31,86.26 34.1,86.46 34.1,87.76 33.9,87.96 33.49,87.96 33.29,87.76 33.29,86.46 33.09,86.26 26.95,86.26 26.34,85.65 16.01,85.65 v1(15.3,86.36)
EMMC_DATA5_R: length 19.6
  TOP w0.127: v1(8.06,95.5) 8.06,95.29 8.44,94.91 U27.F3 U27.E3 U27.D2 U27.C3 U27.B4
  TOP w0.203: v1(12.7,92.2) 13.37,91.53 13.66,91.53 14.04,91.92 14.33,91.92 14.62,91.63 14.62,91.34 14.23,90.96 14.23,90.67 14.52,90.38 14.81,90.38 15.19,90.77 15.48,90.77 15.77,90.48 15.77,90.19 15.38,89.81 15.38,89.52 16.12,88.79 R219.2
  ART03 w0.203: v1(8.06,95.5) 9.89,93.67 9.89,92.18 10.6,91.47 11.96,91.47 v1(12.7,92.2)
EMMC_DATA6: length 69.8
  TOP w0.203: v1(43,59.58) J16.219 ; R38.1 11.1,87.78 R220.1 R205.2 v1(11.2,86.36)
  ART03 w0.203: v1(36.36,83.46) 35.87,82.98 35.87,77.33 42.11,71.09 42.11,64.41 42.37,64.16 42.37,60.21 v1(43,59.58)
  ART04 w0.203: v1(36.36,83.46) 35.88,83.46 35.67,83.26 35.67,82.5 35.47,82.3 35.06,82.3 34.86,82.5 34.86,83.26 34.66,83.46 34.25,83.46 34.05,83.26 34.05,82.5 33.85,82.3 33.44,82.3 33.24,82.5 33.24,83.26 33.03,83.46 32.63,83.46 32.42,83.26 32.42,82.5 32.22,82.3 31.81,82.3 31.61,82.5 31.61,83.26 31.41,83.46 31,83.46 30.8,83.26 30.8,82.5 30.59,82.3 30.19,82.3 29.98,82.5 29.98,83.26 29.78,83.46 29.37,83.46 29.17,83.26 29.17,82.5 28.97,82.3 28.56,82.3 28.36,82.5 28.36,83.26 28.16,83.46 27.75,83.46 27.55,83.26 27.55,82.5 27.34,82.3 26.94,82.3 26.73,82.5 26.73,83.26 26.53,83.46 26.01,83.46 24.86,83.94 15.77,83.94 12.09,85.47 v1(11.2,86.36)
EMMC_DATA6_R: length 12.5
  TOP w0.203: U27.B5 U27.C5 7.56,93.68 v1(7.33,93.92) ; v1(8.38,89.15) 9.04,88.49 11.73,88.49 12.01,88.21 R220.2
  ART04 w0.203: v1(8.38,89.15) 8.36,89.13 7.42,89.13 5.82,90.73 5.82,92.41 v1(7.33,93.92)
EMMC_DATA7: length 78.7
  TOP w0.203: v1(42.5,58.81) J16.221 ; 9.55,86.97 R204.2 R221.1 ; 9.55,86.97 v1(9.55,86.36) ; 9.55,86.97 R38.2
  ART03 w0.203: v1(36.36,84.86) 35.26,83.77 35.26,77.07 41.2,71.14 41.2,64.46 41.76,63.9 41.76,60.15 42.5,59.41 v1(42.5,58.81)
  ART04 w0.203: v1(9.55,86.36) 9.55,85.39 9.35,85.19 8.28,85.19 7.92,85.55 7.92,87.96 8.13,88.16 9.59,88.16 9.79,87.96 9.79,87.5 10,87.3 10.4,87.3 10.61,87.5 10.61,87.96 10.81,88.16 11.8,88.16 12.13,87.84 12.13,87.09 13.45,85.76 15.44,84.94 16.22,84.94 16.5,84.66 17.03,84.66 17.31,84.94 17.85,84.94 18.13,84.66 18.66,84.66 18.94,84.94 19.47,84.94 19.75,84.66 20.28,84.66 20.56,84.94 21.1,84.94 21.38,84.66 21.91,84.66 22.19,84.94 24.85,84.94 25.96,84.48 27.05,84.48 27.26,84.68 27.26,85.37 27.46,85.57 27.87,85.57 28.07,85.37 28.07,84.68 28.27,84.48 28.68,84.48 28.88,84.68 28.88,84.89 29.09,85.09 29.49,85.09 29.7,84.89 29.7,84.68 29.9,84.48 30.3,84.48 30.51,84.68 30.51,85.19 30.77,85.45 31.06,85.45 31.32,85.19 31.32,84.68 31.52,84.48 31.93,84.48 32.13,84.68 32.13,85.37 32.34,85.57 32.74,85.57 32.95,85.37 32.95,84.68 33.15,84.48 33.56,84.48 33.76,84.68 33.76,85.37 33.96,85.57 35.64,85.57 v1(36.36,84.86)
EMMC_DATA7_R: length 6.8
  TOP w0.127: U27.B7 U27.A8
  TOP w0.203: R221.2 8.71,87.96 6.06,90.61 U27.A8 ; U27.B6 U27.B7
EMMC_DS: length 61.7
  TOP w0.203: v1(41.94,83.46) 42.86,82.55 42.86,81.87 43.4,81.33 R222.1 43.69,80.92 44.05,80.56 44.05,79.15 v1(44.69,78.52) ; v1(46.5,58.82) J16.205 ; R78.1 21.92,90.56 v1(22.16,90.81)
  ART03 w0.203: v1(46.5,58.82) 46.5,62.81 46.74,63.04 46.74,72.51 45.29,73.96 45.29,77.92 v1(44.69,78.52)
  ART04 w0.203: v1(22.16,90.81) 22.16,91.49 23.23,92.56 24.51,92.56 24.71,92.76 24.71,94.01 24.92,94.21 25.32,94.21 25.53,94.01 25.53,92.76 25.73,92.56 26.14,92.56 26.34,92.76 26.34,94.01 26.54,94.21 26.95,94.21 27.15,94.01 27.15,93.13 27.35,92.93 34.66,92.93 41.94,85.65 v1(41.94,83.46)
EMMC_DS_R: length 22.4
  TOP w0.127: v1(8.05,96.26) 8.04,96.26 7.69,95.91 U27.H5
  TOP w0.203: v1(22.23,89.53) 22.01,89.75 R78.2
  ART04 w0.203: v1(8.05,96.26) 8.61,95.7 8.61,93.22 7.65,92.25 7.65,91.49 8.18,90.96 10.06,90.96 10.36,90.65 17.68,90.65 18.47,89.86 21.9,89.86 v1(22.23,89.53)
EMMC_POWER_EN: length 96.4
  TOP w0.203: R212.1 50.22,102.23 v1(49.78,102.23) ; R2.1 v1(42.62,118.54) ; J16.197 v1(48.5,58.82)
  ART03 w0.203: v1(42.62,118.54) 42.16,118.54 36.77,113.15 36.77,108.39 40.09,105.06 46.5,105.06 49.33,102.23 v1(49.78,102.23) ; v1(46.64,85.08) 47.35,84.38 47.35,83.49 49.17,81.66 49.17,60.87 48.5,60.2 v1(48.5,58.82)
  ART04 w0.203: v1(46.64,85.08) 47.42,85.86 47.42,95.25 42.01,100.66 42.01,117.93 v1(42.62,118.54)
FAN_PWM0: length 71.9
  TOP w0.203: C309.1 113.94,106.63 R354.1 R348.2 ; J16.288 105.75,49.9 105.41,50.24 v1(105.41,51.28)
  TOP w0.254: R354.1 v1(112.8,107.24)
  ART03 w0.203: v1(105.41,51.28) 105.41,54.95 108.23,57.76 108.23,57.86 109.3,58.93 111.49,58.93 111.92,59.36 111.92,64.36 109.88,66.4 109.88,71.31 110.34,71.77 110.34,77 108.1,79.24 108.1,81.5 108.46,81.86 108.82,81.86 110.13,83.17 110.13,87.69 113.11,90.67 113.11,100.81 114.18,101.88 114.38,101.88 114.66,102.16 114.66,105.38 v1(112.8,107.24)
FAN_PWM_CTRL: length 24.7
  TOP w0.203: Q10.3 119.84,106.93 120.3,106.48 v1(120.83,106.48) 120.88,106.43 120.88,105.46 121.21,105.13 R352.2
  TOP w0.254: R353.1 v1(120.83,106.48)
  ART04 w0.203: v1(120.83,106.48) 120.82,106.48 120.5,106.8 114.19,106.8 111.72,109.27 111.72,111.5 117.35,117.13 J8.2
FAN_STA: length 80.7
  TOP w0.203: C184.1 124.97,107.66 v1(125.07,107.56) 125.07,109.53 125.36,109.82 126.24,109.82 126.56,110.14 R346.1 ; J16.284 106.75,50.83 106.47,51.11 106.47,52.28 v1(106.75,52.55)
  ART03 w0.203: v1(125.07,107.56) 125.39,107.24 125.39,100.34 124.51,99.46 124.51,88.11 124.77,87.85 124.77,86.98 124.79,86.96 124.79,85.28 127.29,82.78 127.29,67.4 124.31,64.42 124.31,61.66 121.22,58.57 118.07,58.57 116.08,56.58 116.08,54.32 114.77,53.01 112.85,53.01 112.54,53.31 107.51,53.31 v1(106.75,52.55)
GATE_24711: length 16.7
  TOP w0.203: v1(103.73,38.54) 103.73,38.79 104.22,39.28 U12.7 106.32,39.28 C213.1
  TOP w0.381: R381.1 101.95,28.37 v1(101.95,27.58)
  ART04 w0.203: v1(103.73,38.54) 101.9,36.71 101.9,27.62 v1(101.95,27.58)
GPIO13: length 44.6
  TOP w0.203: J16.314 99.25,47.41 v1(99.11,47.27) ; R5.1 v1(121.22,68.23)
  ART03 w0.203: v1(99.11,47.27) 100.08,48.23 101.91,48.23 102.62,48.95 104.28,48.95 104.89,49.56 111.46,49.56 112.5,50.6 114.22,50.6 114.73,50.09 v1(120.7,50.09)
  BOTTOM w0.203: v1(121.22,68.23) 121.22,59.01 122.42,57.82 122.42,56.23 120.7,54.52 v1(120.7,50.09)
GPIO13_3V3: length 18.2
  TOP w0.203: v1(120.05,76.1) U21.11 ; v1(123.07,89.12) 123.14,89.12 R56.2
  ART04 w0.203: v1(123.07,89.12) 124.13,88.07 124.13,78.54 121.7,76.1 v1(120.05,76.1)
GPIO16: length 94.1
  TOP w0.203: J16.149 60.5,59.69 61.06,60.25 61.06,67.04 68.77,74.75 79.68,74.75 v1(81.79,72.64) ; R635.1 v1(118.95,56.69) 120.34,55.3 123.71,55.3 125.47,57.06 R292.1
  BOTTOM w0.203: v1(118.95,56.69) 110.54,65.1 110.54,66.32 107.45,69.41 102.35,69.41 98.77,65.84 93.51,65.84 93.05,66.29 84.33,66.29 81.76,68.86 81.76,72.62 v1(81.79,72.64)
GPIO16_3V3: length 60.9
  TOP w0.203: U20.13 119.08,64.58 120.55,63.12 122.65,63.12 v1(123.14,62.63) R64.2 ; R258.1 122.94,103.63 122.94,103.63 v1(122.87,103.63)
  ART03 w0.203: v1(122.87,103.63) 122.01,104.49 122.01,107.04 122.51,107.54 123.23,107.54 124.45,106.33 124.45,105.47 124.55,105.37 124.55,100.07 124.1,99.63 124.1,87.94 124.36,87.68 124.36,86.81 124.38,86.79 124.38,85.12 126.88,82.62 126.88,67.57 123.14,63.83 v1(123.14,62.63)
GPIO17: length 91.4
  TOP w0.203: R237.1 v1(119.88,56.69) 120.79,55.78 123.27,55.78 124.54,57.04 R293.1 ; v1(80.64,72.64) 78.95,74.34 68.94,74.34 61.67,67.08 61.67,60.29 61,59.62 J16.147
  BOTTOM w0.203: v1(119.88,56.69) 110.95,65.63 110.95,66.49 107.62,69.82 102.18,69.82 99.58,67.22 83.98,67.22 82.17,69.03 82.17,72.38 82.25,72.45 82.25,72.83 81.98,73.1 81.1,73.1 v1(80.64,72.64)
GPIO17_3V3: length 14
  TOP w0.203: v1(119.41,67.29) 119.73,66.97 U20.12 ; v1(122.97,74.52) R447.2 123.58,73.6 R65.2
  ART03 w0.203: v1(119.41,67.29) 120.06,67.29 120.55,67.78 122.41,67.78 123.84,69.2 123.84,73.22 122.97,74.08 v1(122.97,74.52)
GPIO22: length 41.8
  TOP w0.203: v1(93.34,51.44) 92.75,50.84 J16.20 ; R294.1 123.61,56.86 122.95,56.21 121.29,56.21 v1(120.81,56.69) R575.1
  ART03 w0.203: v1(93.34,51.44) 92.89,50.98 92.89,50.36 93.99,49.25 101.77,49.25 102.28,49.76 103.94,49.76 104.55,50.37 111.12,50.37 112.95,52.2 115.11,52.2 116.9,53.99 116.9,56.25 117.8,57.15 120.35,57.15 v1(120.81,56.69)
GPIO22_3V3: length 20.8
  TOP w0.203: v1(123.07,78.91) 123.14,78.91 123.63,78.91 123.67,78.95 ; 123.67,78.95 R448.2 ; 123.67,78.95 R236.2 ; v1(120.71,64.52) 120.38,64.84 U20.11
  ART03 w0.203: v1(123.07,78.91) 124.1,77.88 124.1,74.1 125.61,72.59 125.61,68.95 121.18,64.52 v1(120.71,64.52)
GPIO23: length 37.2
  TOP w0.203: v1(121.74,56.69) R637.1 R295.1 ; v1(93.34,50.55) 93.34,49.95 93.25,49.86 J16.18
  ART03 w0.203: v1(121.74,56.69) 120.88,57.56 117.63,57.56 116.5,56.42 116.5,54.16 114.94,52.6 112.78,52.6 110.95,50.77 104.39,50.77 103.78,50.16 102.11,50.16 101.6,49.66 94.23,49.66 v1(93.34,50.55)
GPIO23_3V3: length 15.1
  TOP w0.203: v1(120.71,67.29) 121.03,66.97 U20.10 ; v1(123.07,76.38) R435.1 123.67,76.39 R238.2
  ART03 w0.203: v1(120.71,67.29) 122.5,67.29 124.24,69.03 124.24,73.39 123.7,73.93 123.7,75.76 v1(123.07,76.38)
GPIO24: length 14.1
  TOP w0.203: R636.1 v1(113.22,56.64) ; J16.282 107.25,51.09 v1(107.06,51.28)
  ART03 w0.203: v1(107.06,51.28) 106.29,52.05 106.29,52.98 107.16,53.84 107.16,54.4 107.57,54.81 109.26,54.81 111.08,56.64 v1(113.22,56.64)
GPIO24_3V3: length 24
  TOP w0.203: R440.1 123.14,80.96 v1(123.07,80.96) ; v1(112.85,67.29) 113.17,66.97 U32.13
  ART03 w0.203: v1(123.07,80.96) 122.53,80.42 122.53,79.63 122.11,79.21 122.11,73.8 123.02,72.88 123.02,72.47 122.51,71.96 120.51,71.13 119.76,71.13 117.05,68.42 117.05,68.22 115.67,66.84 113.31,66.84 v1(112.85,67.29)
GPIO25: length 21.3
  TOP w0.203: R674.1 v1(114.33,56.64) ; v1(114.58,54.74) 115.04,54.28 115.04,53.04 114.22,52.22 114.22,48.19 112.73,46.69 105.47,46.69 104.75,47.42 J16.292
  ART03 w0.203: v1(114.33,56.64) 114.33,54.99 v1(114.58,54.74)
GPIO25_3V3: length 31.7
  TOP w0.203: v1(114.15,64.52) 113.82,64.84 U32.12 ; R289.1 123.14,85.11 123.14,85.11 v1(123.07,85.11)
  ART03 w0.203: v1(123.07,85.11) 122.25,85.11 121.5,84.36 121.5,79.31 118.83,76.64 113.18,76.64 112.41,75.87 112.41,67.5 112.39,67.48 112.39,66.86 114.15,65.1 v1(114.15,64.52)
GPIO26: length 19.7
  TOP w0.203: J16.290 105.25,47.62 105.68,47.19 112.52,47.19 113.77,48.44 113.77,52.65 v1(114.58,53.47) ; R669.1 v1(115.44,56.64)
  ART03 w0.203: v1(114.58,53.47) 115.44,54.32 v1(115.44,56.64)
GPIO26_3V3: length 64.2
  TOP w0.203: v1(123.14,61.14) 122.66,61.62 121.05,61.62 118.61,64.06 115.25,64.06 114.47,64.84 U32.11 ; R452.2 122.94,104.65 v1(122.87,104.65)
  ART03 w0.203: v1(122.87,104.65) 122.41,105.11 122.41,106.87 122.68,107.14 123.06,107.14 124.04,106.16 124.04,105.31 124.14,105.2 124.14,100.24 123.7,99.8 123.7,87.77 123.96,87.51 123.96,86.64 123.98,86.62 123.98,84.84 124.51,84.31 124.51,74.27 126.02,72.76 126.02,68.75 122.68,65.41 122.68,61.59 v1(123.14,61.14)
GPIO27: length 71.5
  TOP w0.203: R6.1 109.7,71.86 109.04,71.2 101.57,71.2 98.5,68.13 82.22,68.13 81.74,68.61 70.03,68.61 v1(67.84,70.79) ; J16.191 v1(50,58.08)
  BOTTOM w0.203: v1(50,58.08) 54.24,58.08 54.61,57.71 55.18,57.71 55.98,58.51 55.98,59.01 56.52,59.54 56.52,59.91 63.55,66.94 63.93,67.86 66.17,70.1 v1(67.84,70.79)
GPIO27_3V3: length 4.5
  TOP w0.203: U21.10 120.7,76.51 121.7,75.51 R57.2
HDMI0_CEC: length 56.1
  TOP w0.203: J16.239 38,54.57 v1(38.11,54.46) ; R281.1 v1(64.87,21.11) R280.2
  ART03 w0.203: v1(63.12,26.92) 63.12,30.48 61.29,32.31 57.85,32.31 57.1,33.06 57.1,33.08 56.83,33.35 56.81,33.35 55.73,34.43 55.73,37.35 55.42,37.66 55.42,40.73 55.19,40.96 55.19,41.79 52.36,44.63 49.52,44.63 48.31,45.83 48.31,52.36 47,53.67 38.9,53.67 v1(38.11,54.46)
  ART04 w0.203: v1(63.12,26.92) 63.12,25.48 64.24,24.36 64.24,22.38 64.87,21.75 v1(64.87,21.11)
HDMI0_HOTPLUG: length 86.2
  TOP w0.203: J16.237 38.5,54.78 38.59,54.69 38.59,53.61 v1(38.18,53.19) ; v1(61.69,18.82) 61.95,19.08 R286.2 C142.1 R287.2 R285.1
  ART03 w0.203: v1(38.18,53.19) 38.79,52.58 39.47,52.58 40.21,51.84 40.21,47.04 41.71,45.54 46.54,45.54 50.32,41.77 50.32,40.81 49.39,39.88 48.71,39.6 45.23,39.6 39.72,37.31 38.13,37.31 35.68,34.86 v1(35.68,30.18) ; v1(48.65,19.93) 52.81,15.77 60.33,15.77 61.69,17.14 v1(61.69,18.82)
  ART04 w0.203: v1(48.65,19.93) 44.88,23.7 37.52,23.7 35.58,25.63 35.58,30.09 v1(35.68,30.18)
HDMI0_SCL: length 53.5
  TOP w0.203: R282.1 v1(63.85,21.11) R296.2 ; J16.230 40.25,51.45 v1(40.72,51.92)
  ART03 w0.203: v1(40.72,51.92) 41.35,51.92 42.21,52.78 46.66,52.78 47.45,52 47.45,45.48 49.16,43.76 51.15,43.76 53.57,41.35 53.57,35.57 54.86,34.27 54.86,33.38 56.8,31.44 60.93,31.44 61.67,30.71 v1(61.67,28.73)
  ART04 w0.203: v1(61.67,28.73) 62.53,27.86 62.53,25.2 63.37,24.36 63.37,21.58 v1(63.85,21.11)
HDMI0_SDA: length 85.2
  TOP w0.203: v1(39.45,51.92) 39.45,51.46 39.75,51.16 J16.232 ; R284.2 v1(62.83,21.11) R283.1
  ART03 w0.203: v1(35.76,22.63) 35.48,22.91 35.48,27.42 35.19,28.12 35.19,35.02 37.94,37.77 39.62,37.77 45.14,40.06 48.2,40.06 49.43,40.56 49.86,41 49.86,41.58 48.89,42.55 48.01,42.55 47.47,43.08 47.47,43.48 45.87,45.09 41.52,45.09 39.75,46.85 39.75,51.61 v1(39.45,51.92) ; v1(45.89,21.78) 47.16,20.5 49.43,20.5 53.66,16.28 59.64,16.28 61.06,17.71 61.06,19.34 v1(62.83,21.11)
  ART04 w0.203: v1(35.76,22.63) 36.83,22.63 37.06,22.4 40.16,22.4 40.69,22.94 44.73,22.94 v1(45.89,21.78)
HDMI0_TX0_C_N: length 6.1
  TOP w0.155: R256.2 67.03,14.96 66.67,14.61 65.96,14.61 65.52,14.17 D15.7 D15.4 65.52,12.54 65.19,12.2 65.19,12.17 64.87,11.84 J6.9
HDMI0_TX0_C_P: length 6.2
  TOP w0.155: R255.2 67.94,14.93 67.23,14.22 66.28,14.22 66.02,13.97 D15.6 D15.5 66.02,12.28 66.06,12.25 66.06,11.84 65.87,11.66 J6.7
HDMI0_TX0_N: length 58.1
  TOP w0.155: v1(42.54,52.3) 42.81,52.03 42.81,49.78 42.75,49.73 J16.220 ; R256.1 67.28,16.15 67.28,16.37 v1(67.03,16.61)
  ART04 w0.14: v1(67.03,16.61) 67.28,16.86 67.28,17.43 67.65,17.8 67.83,17.8 68,17.97 68,18.26 67.83,18.43 67.65,18.43 67.28,18.8 67.28,19.46 67.65,19.83 67.83,19.83 68,20 68,20.29 67.83,20.46 67.65,20.46 67.28,20.84 67.28,21.49 67.65,21.86 67.83,21.86 68,22.03 68,22.33 67.83,22.5 67.65,22.5 67.28,22.87 67.28,23.52 67.65,23.89 67.83,23.89 68,24.06 68,24.36 67.83,24.53 67.65,24.53 67.28,24.9 67.28,25.57 66.56,27.31 65.33,28.54 64.02,29.08 62.16,30.94 62.16,30.94 61.82,31.08 59.56,33.34 56.19,33.34 54.87,34.66 52.3,35.73 51.14,36.9 50.09,36.9 49.46,37.53 49.23,38.09 48.34,38.98 45.08,40.33 44.6,40.8 44.6,43.75 44.09,44.98 43.26,46.22 42.83,47.25 42.83,48.47 42.65,48.65 42.65,49.09 42.83,49.28 42.83,52 v1(42.54,52.3)
HDMI0_TX0_P: length 57.9
  TOP w0.155: v1(67.94,16.61) 67.69,16.37 67.69,16.15 R255.1 ; v1(43.46,52.3) 43.19,52.03 43.19,49.76 43.25,49.7 J16.218
  ART04 w0.14: v1(43.46,52.3) 43.22,52.05 43.22,47.37 43.61,46.41 44.45,45.16 44.98,43.87 44.98,40.98 45.3,40.66 48.56,39.31 49.56,38.31 49.8,37.75 50.27,37.28 51.32,37.28 52.53,36.06 55.1,35 56.37,33.72 59.74,33.72 62.05,31.42 62.39,31.28 64.24,29.42 65.55,28.88 66.9,27.53 67.66,25.69 67.66,25.08 67.83,24.91 68.01,24.91 68.38,24.54 68.38,23.88 68.01,23.51 67.83,23.51 67.66,23.34 67.66,23.05 67.83,22.88 68.01,22.88 68.38,22.51 68.38,21.85 68.01,21.48 67.83,21.48 67.66,21.31 67.66,21.01 67.83,20.84 68.01,20.84 68.38,20.47 68.38,19.82 68.01,19.45 67.83,19.45 67.66,19.28 67.66,18.98 67.83,18.81 68.01,18.81 68.38,18.44 68.38,17.79 68.01,17.42 67.83,17.42 67.66,17.25 67.66,16.89 v1(67.94,16.61)
HDMI0_TX1_C_N: length 6.6
  TOP w0.155: R310.2 69.71,14.86 69.37,14.86 D13.10 D13.1 67.01,12.49 66.8,12.49 66.43,12.12 66.43,11.73 66.37,11.67 J6.6
HDMI0_TX1_C_P: length 6.6
  TOP w0.155: J6.4 67.37,12.32 67.94,12.89 68.01,12.89 68.02,12.88 68.09,12.88 68.12,12.92 68.14,12.92 D13.2 D13.9 69.7,14.48 70.24,14.48 R311.2
HDMI0_TX1_N: length 56.6
  TOP w0.155: R310.1 70.19,16.15 70.19,16.37 v1(69.95,16.61) ; J16.214 44.25,49.73 44.32,49.8 44.32,50.57 v1(44.04,50.85)
  ART04 w0.14: v1(44.04,50.85) 44.29,50.6 44.29,49.83 44.76,48.68 45.55,47.89 47.13,44.08 47.13,42.76 48.5,41.39 48.5,40.7 49.24,39.97 50.53,39.97 53.19,37.31 55.96,36.16 58.02,36.16 59.4,35.89 61.21,34.08 61.72,32.84 62.57,31.99 62.99,31.82 66.17,29.69 67.06,28.8 67.62,28.8 67.76,28.94 67.96,28.94 68.2,28.71 68.2,28.5 68.06,28.36 68.06,27.8 69.14,26.72 69.26,26.44 69.26,26.12 69.63,25.75 69.69,25.75 69.86,25.58 69.86,25.28 69.69,25.11 69.63,25.11 69.26,24.74 69.26,24.09 69.63,23.72 69.69,23.72 69.86,23.55 69.86,23.25 69.69,23.08 69.63,23.08 69.26,22.71 69.26,22.06 69.63,21.68 69.69,21.68 69.86,21.51 69.86,21.22 69.69,21.05 69.63,21.05 69.26,20.68 69.26,20.16 69.6,19.33 70.11,19.12 71.12,19.54 71.32,19.45 71.44,19.17 71.36,18.96 70.35,18.55 70.13,18.04 70.25,17.77 70.25,16.91 v1(69.95,16.61)
HDMI0_TX1_P: length 56.5
  TOP w0.155: v1(44.96,50.85) 44.7,50.59 44.7,49.74 44.75,49.7 J16.212 ; R311.1 70.61,16.15 70.61,16.37 v1(70.85,16.61)
  ART04 w0.14: v1(44.96,50.85) 44.67,50.56 44.67,49.95 45.1,48.91 45.89,48.12 47.51,44.19 47.51,42.94 48.88,41.57 48.88,40.88 49.42,40.35 50.71,40.35 53.41,37.65 56.08,36.54 58.14,36.54 59.59,36.25 61.54,34.3 62.06,33.07 62.8,32.33 63.18,32.17 66.42,30 67.24,29.18 67.44,29.18 67.58,29.32 68.14,29.32 68.58,28.89 68.58,28.32 68.44,28.19 68.44,27.98 69.48,26.95 69.64,26.56 69.64,26.3 69.81,26.13 69.87,26.13 70.24,25.76 70.24,25.1 69.87,24.73 69.81,24.73 69.64,24.56 69.64,24.27 69.81,24.1 69.87,24.1 70.24,23.72 70.24,23.07 69.87,22.7 69.81,22.7 69.64,22.53 69.64,22.23 69.81,22.06 69.87,22.06 70.24,21.69 70.24,21.04 69.87,20.67 69.81,20.67 69.64,20.5 69.64,20.27 69.91,19.63 70.11,19.55 71.12,19.97 71.62,19.76 71.87,19.16 71.66,18.66 70.65,18.24 70.56,18.04 70.63,17.89 70.63,16.84 v1(70.85,16.61)
HDMI0_TX2_C_N: length 8.6
  TOP w0.155: R312.2 72.75,14.83 72.75,14.15 72.55,13.95 70.74,13.95 70.31,13.51 70.15,13.51 D13.7 D13.4 69.11,12.47 69.03,12.47 68.88,12.33 68.69,12.33 68.62,12.4 68.19,12.4 67.87,12.08 J6.3
HDMI0_TX2_C_P: length 7.8
  TOP w0.155: J6.1 68.87,11.77 69.11,12.01 69.33,12.01 69.56,12.25 D13.5 D13.6 70.54,13.2 70.54,13.21 70.9,13.57 72.71,13.57 73.14,13.99 73.14,14.83 R313.2
HDMI0_TX2_N: length 55.6
  TOP w0.155: v1(72.49,16.61) 72.74,16.37 72.74,16.15 R312.1 ; v1(45.54,52.3) 45.81,52.03 45.81,49.78 45.75,49.73 J16.208
  ART04 w0.14: v1(45.54,52.3) 45.8,52.03 45.8,50.08 46.35,48.75 47.41,47.7 48.84,44.24 48.84,43.06 50.54,41.36 50.8,41.36 53.32,38.84 54.5,38.36 55.84,38.36 61.12,36.17 63.03,36.17 63.64,35.92 64.18,35.38 64.25,35.22 64.25,33.32 64.27,33.26 64.47,32.79 65.97,31.29 69.44,29.85 70.28,29.02 71.7,25.58 71.7,22.26 72.38,20.63 72.38,17.75 72.76,17.36 72.76,16.88 v1(72.49,16.61)
HDMI0_TX2_P: length 56.4
  TOP w0.155: J16.206 46.25,49.7 46.19,49.76 46.19,49.8 46.19,52.03 v1(46.46,52.3) ; R313.1 73.15,16.15 73.15,16.37 v1(73.4,16.61)
  ART04 w0.14: v1(73.4,16.61) 73.14,16.87 73.14,17.54 72.76,17.93 72.76,20.75 72.08,22.38 72.08,22.66 72.25,22.82 72.31,22.82 72.47,22.98 72.47,23.28 72.31,23.44 72.25,23.44 72.08,23.6 72.08,23.9 72.25,24.06 72.31,24.06 72.47,24.21 72.47,24.52 72.31,24.68 72.25,24.68 72.08,24.84 72.08,25.69 70.61,29.24 69.67,30.19 66.19,31.63 64.8,33.02 64.63,33.43 64.63,35.33 64.52,35.61 63.87,36.26 63.15,36.55 61.24,36.55 55.96,38.74 54.61,38.74 53.54,39.18 50.98,41.74 50.72,41.74 49.22,43.24 49.22,44.35 47.74,47.92 46.69,48.97 46.18,50.19 46.18,52.02 v1(46.46,52.3)
HDMI0_TX_5V: length 13.6
  TOP w0.203: v1(63.91,17.17) 63.68,16.94 U28.5 ; R296.1 R284.1 v1(62.83,23.27) ; v1(58.8,12.57) 59.74,12.57 60.37,11.95 J6.18
  TOP w0.254: v1(62.83,23.27) 62.83,23.52 63.78,24.47 63.78,25.68 D17.3 63.09,25.76 C141.1 62.26,24.49 61.14,23.37 R285.2
HDMI0_TX_CEC: length 10.6
  TOP w0.203: R281.2 64.87,17.57 64.46,17.17 64.16,16.71 63.93,16.49 63.82,16.49 63.33,15.99 U28.4 62.95,14.81 62.87,14.73 v1(62.87,14.22) 62.69,14.05 62.69,11.85 62.87,11.67 J6.13
HDMI0_TX_DDC_SCL_C: length 10.6
  TOP w0.203: R282.2 63.37,19.18 63.37,18.32 U28.6 62.32,17.89 62.03,17.59 62.03,15.04 61.82,14.83 v1(61.82,14.27) 61.87,14.23 J6.15
HDMI0_TX_DDC_SDA_C: length 11.2
  TOP w0.203: J6.16 61.37,13.16 60.79,13.74 60.79,14.41 v1(60.68,14.51) 60.68,15.19 60.5,15.37 U28.3 61.37,15.99 61.52,16.14 61.52,17.96 62.83,19.27 R283.2
HDMI0_TX_HPD_C: length 12.9
  TOP w0.203: U28.1 v1(60.5,18.57) 60.95,18.57 61.14,18.76 R286.1 ; v1(59.36,11.96) 59.44,11.96 59.87,11.53 J6.19
  BOTTOM w0.203: v1(60.5,18.57) 60.5,15.41 58.06,12.98 58.06,12.27 58.37,11.96 v1(59.36,11.96)
HDMI0_TXC_C_N: length 5.3
  TOP w0.155: R331.2 64.72,14.97 64.02,14.27 D15.10 D15.1 63.62,12.38 63.44,12.21 63.37,12.03 J6.12
HDMI0_TXC_C_P: length 5.5
  TOP w0.155: R332.2 64.98,14.45 64.74,14.45 64.52,14.23 D15.9 D15.2 64.52,12.74 64.21,12.42 64.21,12.19 64.37,11.81 J6.10
HDMI0_TXC_N: length 58.5
  TOP w0.155: v1(64.72,16.61) 64.96,16.37 64.96,16.15 R331.1 ; J16.226 41.25,49.73 41.31,49.78 41.31,50.58 v1(41.04,50.85)
  ART04 w0.14: v1(41.04,50.85) 41.33,50.56 41.33,49.6 41.07,49.34 41.07,48.97 41.33,48.71 41.33,45.5 40.47,44.64 39.53,44.64 39.16,44.27 39.16,43.61 39.53,43.24 40.47,43.24 40.69,43.02 41.18,41.85 41.07,41.58 40.59,41.38 40.38,40.87 40.62,40.28 41.13,40.07 41.61,40.27 41.81,40.19 41.87,40.05 42.37,39.54 42.93,39.54 43.47,40.09 43.68,40.09 43.91,39.85 43.91,39.65 43.37,39.11 43.37,38.54 45.21,36.7 45.96,36.39 48.07,36.39 48.89,35.57 48.89,35.04 49.41,34.51 51.77,33.54 52.93,33.54 58.33,31.3 59.45,30.55 60.31,30.19 62.95,28.43 64.35,26.34 65.31,24 65.58,22.67 65.58,19.83 65,18.44 65,16.9 v1(64.72,16.61)
